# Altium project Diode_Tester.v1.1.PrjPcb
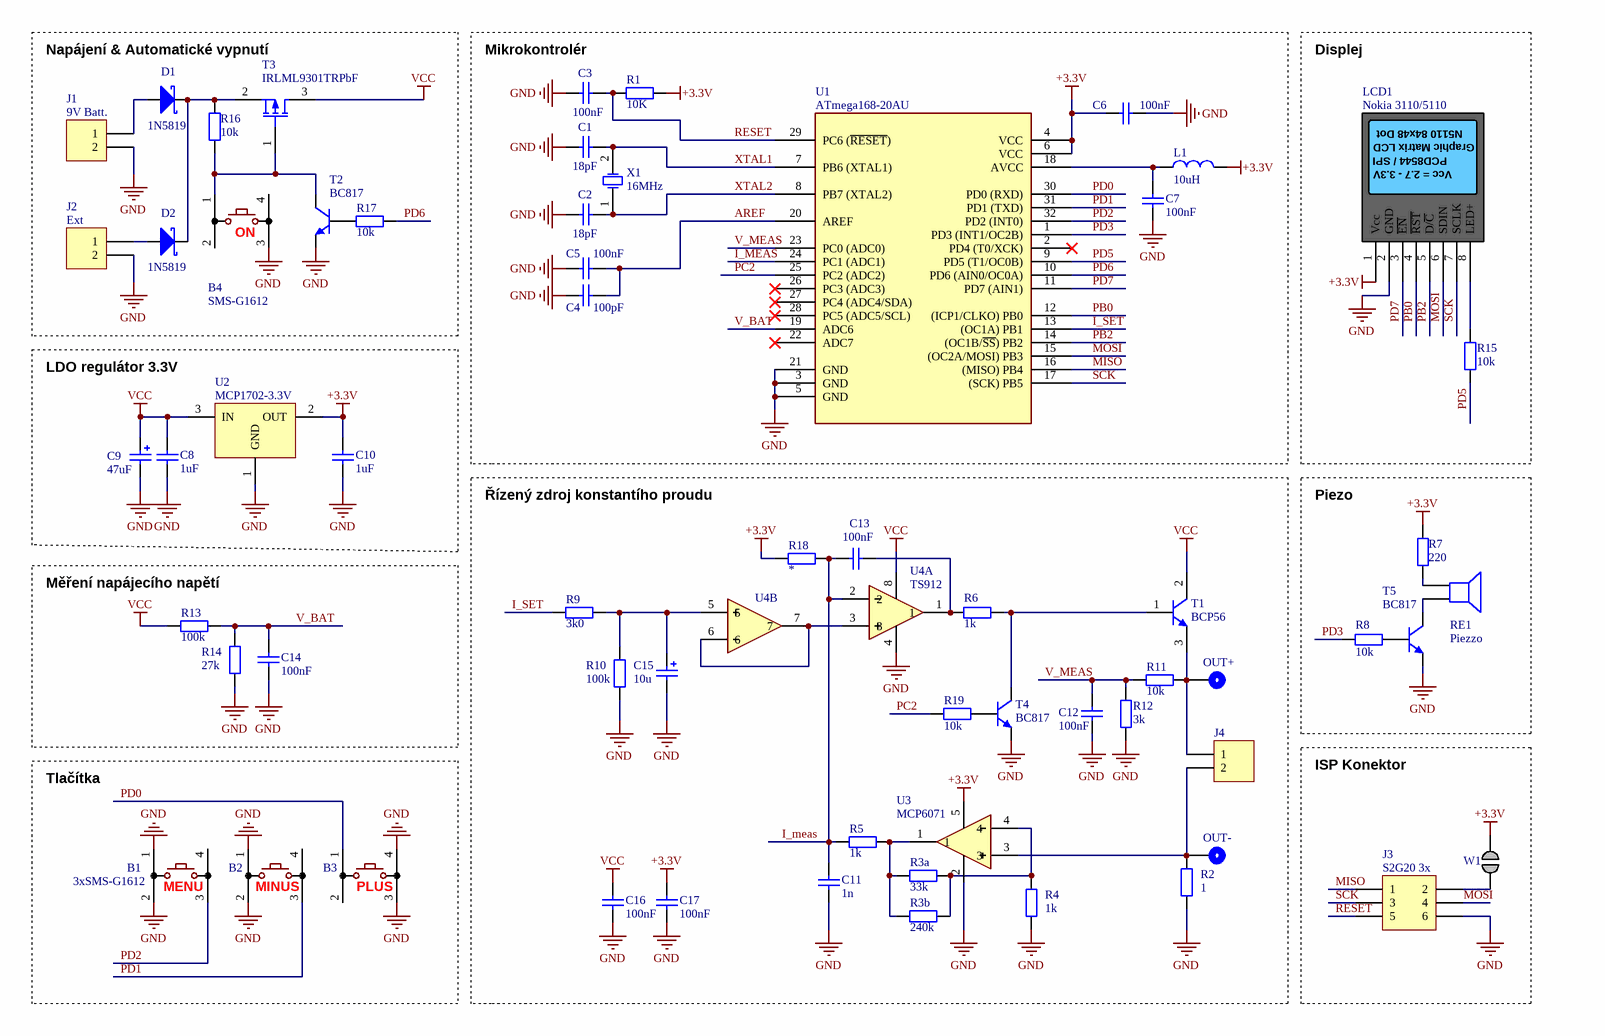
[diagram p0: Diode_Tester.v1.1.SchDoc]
1 sheet, 63 parts. Net scope: global (net labels, ports and power ports of the same name join across sheets).
Board file: Diode_Tester.v1.1.PcbDoc

## Sheet Diode_Tester.v1.1.SchDoc: Mini Servo Tester
size A4; Date: 28.3.2010; DrawnBy: Miroslav Batek; DocumentNumber: Servo Tester; Revision: 1; SheetNumber: 1; SheetTotal: 1; PageSetup: Record=PageOptionsŽCenterHorizontal=TrueŽCenterVertical=TrueŽPrintScale=1.00ŽXCorrection=1.00ŽYCorrection=1.00ŽPrintKind=0ŽBorderSize=5000000ŽLeftOffset=0ŽBottomOffset=0ŽOrientation=2ŽPaperLength=1000ŽPaperWidth=1000ŽScale=100ŽPaperSource=7ŽPrintQuality=-4ŽMediaType=1ŽDitherType=10ŽPaperKind=A4ŽPrintScaleMode=1

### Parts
B1  3xSMS-G1612  [TACTM-24N-F2]
B2  SMS-G1612  [TACTM-24N-F2]  (value not drawn)
B3  SMS-G1612  [TACTM-24N-F2]  (value not drawn)
B4  SMS-G1612  [TACTM-24N-F2]
C1  value 18pF  [C1206]  (hidden comment: Cap)
C2  value 18pF  [C1206]  (hidden comment: Cap)
C3  value 100nF  [C1206]  (hidden comment: Cap)
C4  value 100pF  [C1206]  (hidden comment: Cap)
C5  value 100nF  [C1206]  (hidden comment: Cap)
C6  value 100nF  [C1206]  (hidden comment: Cap)
C7  value 100nF  [C1206]  (hidden comment: Cap)
C8  value 1uF  [3216[1206]]  (hidden comment: Cap)
C9  value 47uF  [6332[2512]_POL]  (hidden comment: Cap Pol2)
C10  value 1uF  [3216[1206]]  (hidden comment: Cap)
C11  value 1n  [C1206]  (hidden comment: Cap)
C12  value 100nF  [C1206]  (hidden comment: Cap)
C13  value 100nF  [C1206]  (hidden comment: Cap)
C14  value 100nF  [C1206]  (hidden comment: Cap)
C15  value 10u  [6332[2512]_POL]  (hidden comment: Cap Pol2)
C16  value 100nF  [C1206]  (hidden comment: Cap)
C17  value 100nF  [C1206]  (hidden comment: Cap)
D1  1N5819  [MELF2]
D2  1N5819  [MELF2]
J1  9V Batt.  [Battery Cable]
J2  Ext  [J_HDR2X1]
J3  S2G20 3x  [HDR2X3]
J4  Ext  [J_HDR2X1]  (value not drawn)
L1  10uH  [AXIAL]
LCD1  Nokia 3110/5110  [N5110LCD]
OUT+  Test Point  [HOLE 6.0/3.2]  (value not drawn)
OUT-  Test Point  [HOLE 6.0/3.2]  (value not drawn)
R1  value 10K  [3216[1206]]  (hidden comment: Res2)
R2  value 1  [3216[1206]]  (hidden comment: Res2)
R3a  value 33k  [3216[1206]]  (hidden comment: Res2)
R3b  value 240k  [3216[1206]]  (hidden comment: Res2)
R4  value 1k  [3216[1206]]  (hidden comment: Res2)
R5  value 1k  [3216[1206]]  (hidden comment: Res2)
R6  value 1k  [3216[1206]]  (hidden comment: Res2)
R7  value 220  [3216[1206]]  (hidden comment: Res2)
R8  value 10k  [3216[1206]]  (hidden comment: Res2)
R9  value 3k0  [3216[1206]]  (hidden comment: Res2)
R10  value 100k  [3216[1206]]  (hidden comment: Res2)
R11  value 10k  [3216[1206]]  (hidden comment: Res2)
R12  value 3k  [3216[1206]]  (hidden comment: Res2)
R13  value 100k  [3216[1206]]  (hidden comment: Res2)
R14  value 27k  [3216[1206]]  (hidden comment: Res2)
R15  value 10k  [3216[1206]]  (hidden comment: Res2)
R16  value 10k  [3216[1206]]  (hidden comment: Res2)
R17  value 10k  [3216[1206]]  (hidden comment: Res2)
R18  Res2  [3216[1206]]  (value not drawn)
R19  value 10k  [3216[1206]]  (hidden comment: Res2)
RE1  Piezzo  [KPB1220 Small]
T1  BCP56  [SOT223]
T2  BC817  [SOT23-3]
T3  IRLML9301TRPbF  [SOT23-3]
T4  BC817  [SOT23-3]
T5  BC817  [SOT23-3]
U1  ATmega168-20AU  [TQFP32_N]
U2  MCP1702-3.3V  [SOT23-3]
U3  MCP6071  [SOT23-5]
U4  TS912  [SO8_M]  (parts A,B of 2)
W1  Solder Bridge  [Solder Bridge]  (value not drawn)
X1  16MHz  [HC49]

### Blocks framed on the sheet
Napájení & Automatické vypnutí: B4 D1 D2 J1 J2 R16 R17 T2 T3
Mikrokontrolér: C1-C7 L1 R1 U1 X1
Displej: LCD1 R15
LDO regulátor 3.3V: C8-C10 U2
Řízený zdroj konstantího proudu: C11-C13 C15-C17 J4 OUT+ OUT- R2 R3a R3b R4-R6 R9-R12 R18 R19 T1 T4 U3 U4
Piezo: R7 R8 RE1 T5
Měření napájecího napětí: C14 R13 R14
Tlačítka: B1-B3
ISP Konektor: J3 W1

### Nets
+3.3V: C6.2 C10.1 C17.1 L1.2 LCD1.1(Vcc) R1.2 R7.1 R18.1 U1.4(VCC) U1.6(VCC) U2.2(OUT) U3.5 W1.2
GND: B1.1 B1.2 B2.1 B2.2 B3.3 B3.4 B4.3 C1.1 C2.1 C3.2 C4.2 C5.1 C6.1 C7.1 C8.2 C9.2 C10.2 C11.2 C12.1 C14.2 C15.2 C16.2 C17.2 J1.2 J2.2 J3.6 LCD1.2(GND) R2.2 R4.2 R10.1 R12.2 R14.1 T2.2(E) T4.2(E) T5.2(E) U1.3(GND) U1.5(GND) U1.21(GND) U2.1(GND) U3.2 U4.4
VCC: C8.1 C9.1 C16.1 R13.1 T1.2(C) T3.3(D) U2.3(IN) U4.8
AREF: C4.1 C5.2 U1.20(AREF)
I_meas: C11.1 C13.2 R5.1 R18.2 U1.24(PC1_(ADC1)) U4.2
I_SET: R9.1 U1.13((OC1A)_PB1)
MISO: J3.1 U1.16((MISO)_PB4)
MOSI: J3.4 LCD1.6(SDIN) U1.15((OC2A/MOSI)_PB3)
PB0: LCD1.4(~{RST}) U1.12((ICP1/CLKO)_PB0)
PB2: LCD1.5(D/~{C}) U1.14((OC1B/~{SS})_PB2)
PC2: R19.1 U1.25(PC2_(ADC2))
PD0: B3.1 U1.30(PD0_(RXD))
PD1: B2.3 U1.31(PD1_(TXD))
PD2: B1.3 U1.32(PD2_(INT0))
PD3: R8.2 U1.1(PD3_(INT1/OC2B))
PD5: R15.1 U1.9(PD5_(T1/OC0B))
PD6: R17.1 U1.10(PD6_(AIN0/OC0A))
PD7: LCD1.3(~{EN}) U1.11(PD7_(AIN1))
RESET: C3.1 J3.5 R1.1 U1.29(PC6_(~{RESET}))
SCK: J3.3 LCD1.7(SCLK) U1.17((SCK)_PB5)
V_BAT: C14.1 R13.2 R14.2 U1.19(ADC6)
V_MEAS: C12.2 R11.2 R12.1 U1.23(PC0_(ADC0))
XTAL1: C1.2 U1.7(PB6_(XTAL1)) X1.2(OSC2)
XTAL2: C2.2 U1.8(PB7_(XTAL2)) X1.1(OSC1)
NetB4_1: B4.1 R16.1 T2.3(C) T3.1(G)
NetC7_2: C7.2 L1.1 U1.18(AVCC)
NetC13_1: C13.1 R6.1 U4.1
NetC15_1: C15.1 R9.2 R10.2 U4.5
NetD1_1: D1.1(A) J1.1
NetD1_2: D1.2(K) D2.2(K) R16.2 T3.2(S)
NetD2_1: D2.1(A) J2.1
NetJ3_2: J3.2 W1.1
NetJ4_1: J4.1 OUT+.1 R11.1 T1.3(E)
NetJ4_2: J4.2 OUT-.1 R2.1 U3.3
NetLCD1_8: LCD1.8(LED+) R15.2
NetR3a_1: R3a.1 R3b.1 R5.2 U3.1
NetR3a_2: R3a.2 R3b.2 R4.1 U3.4
NetR6_2: R6.2 T1.1(B) T4.3(C)
NetR7_2: R7.2 RE1.1
NetR8_1: R8.1 T5.1(B)
NetR17_2: R17.2 T2.1(B)
NetR19_2: R19.2 T4.1(B)
NetRE1_2: RE1.2 T5.3(C)
NetU4_3: U4.3 U4.6 U4.7

Not connected (* = marked no-connect by the designer): B1 4; B2 4; B3 2; B4 2 4; U1 2(PD4_(T0/XCK))* 22(ADC7)* 26(PC3_(ADC3))* 27(PC4_(ADC4/SDA))* 28(PC5_(ADC5/SCL))*

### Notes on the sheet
- (near B4) ON
- (near B1) MENU
- (near B2) MINUS
- (near B3) PLUS

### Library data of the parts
B1-B4 = Button
C1-C8 C10-C14 C16 C17 = Cap: Capacitor
C9 C15 = Cap Pol2: Polarized Capacitor (Axial)
D1 D2 = Diode 11DQ03: Schottky Rectifier
J1 J2 J4 = Header 2: Header, 2-Pin
J3 = Header 3X2: Header, 3-Pin, Dual row
L1 = Inductor
LCD1 = N5110LCD
R1 R2 R3a R3b R4-R19 = Res2: Resistor
RE1 = Speaker: Loudspeaker
T1 = NPN: NPN Bipolar Transistor
T2 T4 T5 = BC846B: NPN General-purpose Transistor
T3 = MOSFET-P: P-Channel MOSFET; PackageDocument: 1995/1996
U1 = ATmega48/88/168_TQFP_B: ATmega48/88/168
U2 = MCP1702: Note: Pin 2 is electrically connected to Pin 4 (TAB)
U3 = OpAmp Single 3: OpAmp
U4 = OpAmp Dual 2: OpAmp
X1 = XTAL: Crystal Oscillator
